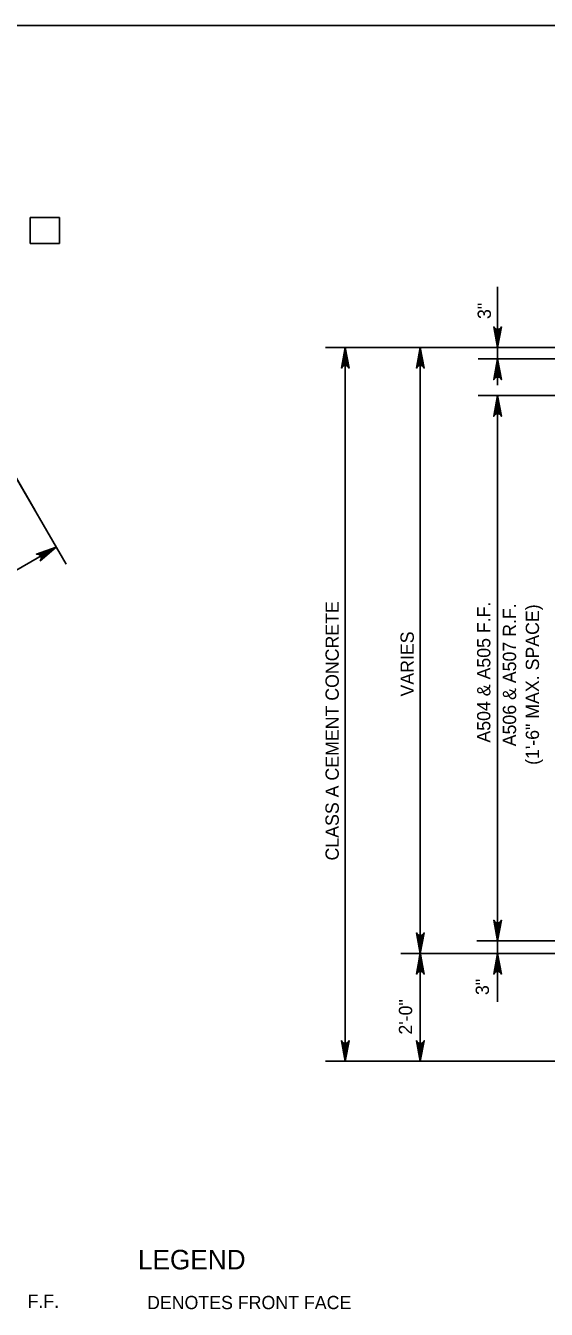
# Model space of a CAD drawing. Extents: x 638255 to 640306, y 296059 to 298435.
# Drawn here: x 638944.1 to 639061.7, y 296942.2 to 297232.5 of the extents above; entities that cross this region are included whole.
import ezdxf

# ---------------------------------------------------------------- set-up
doc = ezdxf.new("R2010")
doc.units = 0
for name, color, linetype in [('2', 7, 'Continuous'), ('Level 3', 7, 'Continuous'), ('Level 4', 7, 'Continuous')]:
    doc.layers.add(name, color=color, linetype=linetype)

msp = doc.modelspace()

# ---------------------------------------------------------------- linework, layer by layer
at = {"layer": '2'}
msp.add_line((638475.46, 297232.46), (639261.46, 297232.46), dxfattribs=at)
at = {"layer": 'Level 3'}
for p, q in [((638945.1, 297183.21), (638945.1, 297189.11)), ((638945.1, 297189.11), (638951.68, 297189.11)), ((638951.68, 297183.21), (638951.68, 297189.11)), ((638951.68, 297183.21), (638945.1, 297183.21)), ((639050.67, 297157.09), (639050.67, 297173.41)), ((638918.6, 297170.64), (638946.21, 297122.8)), ((639050.67, 297159.7), (639050.67, 297165.6)), ((639045.55, 297159.7), (639011.83, 297159.7)), ((639016.25, 296998.29), (639016.25, 297159.7)), ((639115.78, 297159.7), (639028.8, 297159.7)), ((639033.22, 297159.7), (639033.22, 297091.19)), ((639033.22, 297159.7), (639033.22, 297159.7)), ((639063.89, 297159.7), (639046.25, 297159.7)), ((639119.22, 297157.09), (639046.25, 297157.09)), ((639050.67, 297157.09), (639050.67, 297151.2)), ((639115.8, 297148.81), (639046.25, 297148.81)), ((639050.67, 297148.81), (639050.67, 297025.52)), ((638940.68, 297132.38), (638953.19, 297110.73)), ((638950.98, 297114.55), (638874.17, 297070.21)), ((639033.22, 297022.68), (639033.22, 297091.19)), ((639068.31, 297025.52), (639045.98, 297025.52)), ((639050.67, 297025.52), (639050.67, 297011.76)), ((639084.32, 297022.68), (639028.8, 297022.68)), ((639033.22, 296998.29), (639033.22, 297022.68)), ((639058.8, 297022.68), (639046.25, 297022.68)), ((639050.67, 297019.73), (639050.67, 297016.78)), ((639042.28, 296998.29), (639011.83, 296998.29))]:
    msp.add_line(p, q, dxfattribs=at)
for points in [[(639050.67, 297159.7), (639049.8, 297164.35), (639050.05, 297164), (639050.36, 297163.81), (639050.67, 297163.76), (639050.99, 297163.81), (639051.3, 297164), (639051.54, 297164.35), (639050.67, 297159.7), (639051.3, 297164), (639050.99, 297163.81), (639050.67, 297159.7), (639050.67, 297163.76), (639050.36, 297163.81), (639050.67, 297159.7), (639050.05, 297164)], [(639016.25, 297159.7), (639017.12, 297155.05), (639016.87, 297155.41), (639016.56, 297155.59), (639016.25, 297155.65), (639015.94, 297155.59), (639015.63, 297155.41), (639015.38, 297155.05), (639016.25, 297159.7), (639015.63, 297155.41), (639015.94, 297155.59), (639016.25, 297159.7), (639016.25, 297155.65), (639016.56, 297155.59), (639016.25, 297159.7), (639016.87, 297155.41)], [(639033.22, 297159.7), (639034.09, 297155.05), (639033.84, 297155.41), (639033.53, 297155.59), (639033.22, 297155.65), (639032.91, 297155.59), (639032.6, 297155.41), (639032.35, 297155.05), (639033.22, 297159.7), (639032.6, 297155.41), (639032.91, 297155.59), (639033.22, 297159.7), (639033.22, 297155.65), (639033.53, 297155.59), (639033.22, 297159.7), (639033.84, 297155.41)], [(639050.67, 297157.09), (639051.54, 297152.44), (639051.3, 297152.8), (639050.99, 297152.98), (639050.67, 297153.04), (639050.36, 297152.98), (639050.05, 297152.8), (639049.8, 297152.44), (639050.67, 297157.09), (639050.05, 297152.8), (639050.36, 297152.98), (639050.67, 297157.09), (639050.67, 297153.04), (639050.99, 297152.98), (639050.67, 297157.09), (639051.3, 297152.8)], [(639050.67, 297148.81), (639051.54, 297144.16), (639051.3, 297144.52), (639050.99, 297144.71), (639050.67, 297144.76), (639050.36, 297144.71), (639050.05, 297144.52), (639049.8, 297144.16), (639050.67, 297148.81), (639050.05, 297144.52), (639050.36, 297144.71), (639050.67, 297148.81), (639050.67, 297144.76), (639050.99, 297144.71), (639050.67, 297148.81), (639051.3, 297144.52)], [(638950.98, 297114.55), (638946.51, 297112.98), (638946.95, 297112.95), (638947.26, 297112.77), (638947.46, 297112.53), (638947.57, 297112.23), (638947.57, 297111.87), (638947.38, 297111.47), (638950.98, 297114.55), (638947.57, 297111.87), (638947.57, 297112.23), (638950.98, 297114.55), (638947.46, 297112.53), (638947.26, 297112.77), (638950.98, 297114.55), (638946.95, 297112.95)], [(639050.67, 297025.52), (639049.8, 297030.17), (639050.05, 297029.81), (639050.36, 297029.62), (639050.67, 297029.57), (639050.99, 297029.62), (639051.3, 297029.81), (639051.54, 297030.17), (639050.67, 297025.52), (639051.3, 297029.81), (639050.99, 297029.62), (639050.67, 297025.52), (639050.67, 297029.57), (639050.36, 297029.62), (639050.67, 297025.52), (639050.05, 297029.81)], [(639033.22, 297022.68), (639032.35, 297027.33), (639032.6, 297026.97), (639032.91, 297026.78), (639033.22, 297026.73), (639033.53, 297026.78), (639033.84, 297026.97), (639034.09, 297027.33), (639033.22, 297022.68), (639033.84, 297026.97), (639033.53, 297026.78), (639033.22, 297022.68), (639033.22, 297026.73), (639032.91, 297026.78), (639033.22, 297022.68), (639032.6, 297026.97)], [(639033.22, 297022.68), (639034.09, 297018.02), (639033.84, 297018.38), (639033.53, 297018.57), (639033.22, 297018.62), (639032.91, 297018.57), (639032.6, 297018.38), (639032.35, 297018.02), (639033.22, 297022.68), (639032.6, 297018.38), (639032.91, 297018.57), (639033.22, 297022.68), (639033.22, 297018.62), (639033.53, 297018.57), (639033.22, 297022.68), (639033.84, 297018.38)], [(639050.67, 297022.68), (639051.54, 297018.02), (639051.3, 297018.38), (639050.99, 297018.57), (639050.67, 297018.62), (639050.36, 297018.57), (639050.05, 297018.38), (639049.8, 297018.02), (639050.67, 297022.68), (639050.05, 297018.38), (639050.36, 297018.57), (639050.67, 297022.68), (639050.67, 297018.62), (639050.99, 297018.57), (639050.67, 297022.68), (639051.3, 297018.38)], [(639016.25, 296998.29), (639015.38, 297002.94), (639015.63, 297002.58), (639015.94, 297002.4), (639016.25, 297002.34), (639016.56, 297002.4), (639016.87, 297002.58), (639017.12, 297002.94), (639016.25, 296998.29), (639016.87, 297002.58), (639016.56, 297002.4), (639016.25, 296998.29), (639016.25, 297002.34), (639015.94, 297002.4), (639016.25, 296998.29), (639015.63, 297002.58)], [(639033.22, 296998.29), (639032.35, 297002.94), (639032.6, 297002.58), (639032.91, 297002.4), (639033.22, 297002.34), (639033.53, 297002.4), (639033.84, 297002.58), (639034.09, 297002.94), (639033.22, 296998.29), (639033.84, 297002.58), (639033.53, 297002.4), (639033.22, 296998.29), (639033.22, 297002.34), (639032.91, 297002.4), (639033.22, 296998.29), (639032.6, 297002.58)]]:
    msp.add_lwpolyline(points, dxfattribs=at)
for points in [[(639050.18, 297162.65), (639051.16, 297162.65), (639050.67, 297159.7)], [(639015.76, 297156.76), (639016.74, 297156.76), (639016.25, 297159.7)], [(639033.71, 297156.76), (639032.73, 297156.76), (639033.22, 297159.7)], [(639050.18, 297154.14), (639051.16, 297154.14), (639050.67, 297157.09)], [(639050.18, 297145.87), (639051.16, 297145.87), (639050.67, 297148.81)], [(638948.18, 297113.51), (638948.67, 297112.66), (638950.98, 297114.55)], [(639050.18, 297028.46), (639051.16, 297028.46), (639050.67, 297025.52)], [(639033.71, 297025.62), (639032.73, 297025.62), (639033.22, 297022.68)], [(639033.71, 297019.99), (639032.73, 297019.99), (639033.22, 297022.94)], [(639050.18, 297019.73), (639051.16, 297019.73), (639050.67, 297022.68)], [(639015.76, 297001.24), (639016.74, 297001.24), (639016.25, 296998.29)], [(639033.71, 297001.24), (639032.73, 297001.24), (639033.22, 296998.29)]]:
    msp.add_lwpolyline(points, close=True, dxfattribs=at)
at = {"layer": 'Level 4'}
for p, q in [((639050.67, 297028.46), (639050.67, 297031.41)), ((639026.09, 296998.29), (639084.94, 296998.29))]:
    msp.add_line(p, q, dxfattribs=at)

# ---------------------------------------------------------------- texts
at = {"layer": 'Level 3'}
for s, height, p in [('3"', 3, (639049.16, 297166.13)), ('CLASS A CEMENT CONCRETE', 3.0001, (639014.8, 297043.7)), ('A504 & A505 F.F.', 3.0001, (639049.04, 297070.35)), ('A506 & A507 R.F.', 3.0001, (639054.85, 297069.51)), ('(1\'-6" MAX. SPACE)', 3.0001, (639060.03, 297065.31)), ('VARIES', 3, (639031.75, 297080.77)), ('3"', 3, (639048.72, 297013.27)), ('2\'-0"', 3, (639031.37, 297004.33))]:
    msp.add_text(s, height=height, rotation=90, dxfattribs=at).set_placement(p)
for s, height, p in [('LEGEND', 4.421, (638969.44, 296951.24)), ('F.F.', 3, (638944.5, 296942.54)), ('DENOTES FRONT FACE', 3.0001, (638971.49, 296942.25))]:
    msp.add_text(s, height=height, dxfattribs=at).set_placement(p)

doc.saveas('drawing.dxf')
